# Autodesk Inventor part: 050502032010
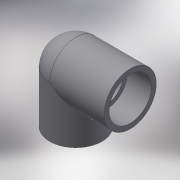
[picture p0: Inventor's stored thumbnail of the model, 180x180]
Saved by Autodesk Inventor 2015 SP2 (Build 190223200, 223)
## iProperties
Created: 2017-10
Part Number: 050502032010
Material: Generic
Description: PLASSON 90° ELBOW THR-CEM PVC 32-1"
Document SubType Name: Modeling
Designer: KIM
Density: 1 g/cm^3
Appearance: Default
Author: KIM
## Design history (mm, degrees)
derived "050502.ipt"
feature "Solid1::050502.ipt"
tag "TaggingFeature1"
workaxis "Work Axis3"
body "Solid1"
other parameters: "d0" = 41, "d1" = 38, "d3" = 39, "d4" = 38, "d6" = 90 deg, "d7" = 30.291, "d9" = 0, "d10" = 32, "d11" = 22, "d12" = 0, "d14" = 24.2328, "d16" = 15.1455, "d17" = 0, "d18" = 0, "d_" = 32, "G_" = 30.291, "E_" = 38, "l_" = 22, "Z_" = 17
